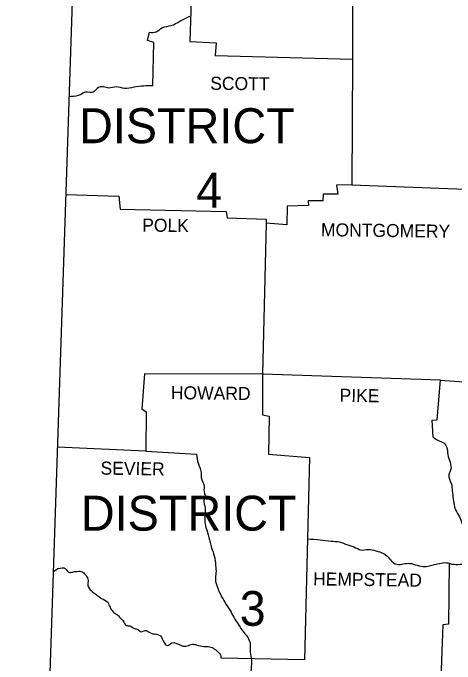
# Model space of a CAD drawing. Extents: x -0.54 to 1.64, y 0 to 0.92.
# Drawn here: x 1.0951 to 1.1608, y 0.624 to 0.7208 of the extents above; entities that cross this region are included whole.
import ezdxf

# ---------------------------------------------------------------- set-up
doc = ezdxf.new("R2010")
doc.units = 0
doc.layers.add('SHET_Annotations', color=7, linetype='Continuous')

msp = doc.modelspace()

# ---------------------------------------------------------------- linework, layer by layer
at = {"layer": 'SHET_Annotations'}
for p, q in [((1.103768, 0.708372), (1.103432, 0.708333)), ((1.101849, 0.638168), (1.101094, 0.637694))]:
    msp.add_line(p, q, dxfattribs=at)
for points in [[(1.095106, 0.817841), (1.104546, 0.741983), (1.100448, 0.618173)], [(1.140413, 0.741231), (1.140102, 0.734721), (1.134163, 0.73467), (1.133825, 0.728731), (1.127964, 0.728886), (1.127783, 0.722792), (1.12161, 0.722714), (1.121403, 0.716593), (1.125319, 0.716386), (1.125163, 0.714493), (1.145576, 0.713932)], [(1.170393, 0.734255), (1.170185, 0.727693), (1.159812, 0.727641), (1.158437, 0.726474), (1.157633, 0.724659), (1.156518, 0.724711), (1.156466, 0.723699), (1.155143, 0.723544), (1.155195, 0.72261), (1.148582, 0.722766), (1.148323, 0.72204), (1.1456, 0.721936), (1.145576, 0.713932)], [(1.115879, 0.70998), (1.116035, 0.716412), (1.115101, 0.716723), (1.115412, 0.717942)], [(1.145576, 0.713932), (1.145522, 0.69525), (1.143214, 0.695198), (1.143421, 0.693849), (1.141217, 0.693875), (1.141165, 0.692864), (1.139012, 0.692864), (1.139064, 0.692163), (1.1359, 0.69206), (1.135822, 0.689285), (1.132736, 0.68957), (1.132218, 0.667111)], [(1.145522, 0.69525), (1.16368, 0.694539)], [(1.102952, 0.693823), (1.110822, 0.693564), (1.111029, 0.691645), (1.126797, 0.691308), (1.126979, 0.690322), (1.132736, 0.690141), (1.132736, 0.68957)], [(1.15867, 0.666203), (1.132218, 0.667111), (1.11466, 0.667137), (1.114271, 0.661924), (1.114893, 0.661483), (1.114868, 0.655622), (1.101707, 0.656223)], [(1.132218, 0.667111), (1.132218, 0.661042), (1.133229, 0.660861), (1.133125, 0.655207), (1.139194, 0.654714), (1.138442, 0.624579), (1.126045, 0.624864)], [(1.157581, 0.657723), (1.157452, 0.660238), (1.158204, 0.66029), (1.15867, 0.666203), (1.165673, 0.665711), (1.165517, 0.662106), (1.174568, 0.661613), (1.174646, 0.659434), (1.182841, 0.658942), (1.184242, 0.656478), (1.183386, 0.655363), (1.183801, 0.653677), (1.204703, 0.652912)], [(1.114868, 0.655622), (1.122414, 0.655207)], [(1.159993, 0.638967), (1.159889, 0.629921), (1.159059, 0.629818), (1.158152, 0.605777)]]:
    msp.add_lwpolyline(points, dxfattribs=at)
for points in [[(1.115412, 0.717942), (1.116398, 0.71802), (1.117357, 0.718642), (1.118628, 0.718953), (1.119925, 0.719602), (1.121531, 0.720372)], [(1.115879, 0.70998), (1.114582, 0.709954), (1.113052, 0.709773), (1.111678, 0.709591), (1.110459, 0.709825), (1.109344, 0.709643), (1.108566, 0.709825), (1.107606, 0.709591), (1.107035, 0.709021), (1.105894, 0.709021), (1.10509, 0.708658), (1.103768, 0.708372)], [(1.157581, 0.657723), (1.158281, 0.657282), (1.159163, 0.656867), (1.15963, 0.656193), (1.159786, 0.655129), (1.160123, 0.653988), (1.160201, 0.652821), (1.159941, 0.652173), (1.160304, 0.650721), (1.160434, 0.649709), (1.16059, 0.648542), (1.160927, 0.646934), (1.161523, 0.645845), (1.162068, 0.644522), (1.162976, 0.64307), (1.163779, 0.64154), (1.164143, 0.640736), (1.164817, 0.63905), (1.165673, 0.637883), (1.167073, 0.636146), (1.168292, 0.634356), (1.168966, 0.633033), (1.17003, 0.631581), (1.171223, 0.630855), (1.172727, 0.630103), (1.173686, 0.62961), (1.17475, 0.628832), (1.176176, 0.62878), (1.177213, 0.62878), (1.178199, 0.628339), (1.17864, 0.627535), (1.17947, 0.626965), (1.180092, 0.626809)], [(1.122414, 0.655207), (1.122648, 0.653833), (1.123063, 0.652614), (1.123089, 0.651732), (1.12353, 0.650358), (1.123504, 0.649865), (1.123659, 0.648827), (1.123478, 0.648309), (1.123685, 0.647219), (1.123659, 0.646364), (1.123633, 0.645689), (1.123711, 0.644548), (1.124048, 0.643537), (1.124411, 0.642059), (1.124645, 0.641255), (1.125034, 0.640062), (1.125241, 0.638609), (1.125293, 0.637546), (1.125215, 0.636535), (1.125501, 0.635393), (1.125993, 0.634252), (1.126616, 0.633163), (1.127394, 0.631918), (1.127938, 0.630933), (1.128613, 0.629895), (1.129157, 0.62904), (1.130013, 0.627924), (1.130376, 0.627017), (1.130376, 0.625772), (1.130558, 0.624553), (1.130506, 0.623256), (1.130428, 0.622037), (1.130091, 0.620429), (1.130298, 0.619651), (1.13118, 0.61851), (1.131725, 0.618173), (1.132684, 0.617992), (1.133125, 0.617343), (1.133411, 0.61641), (1.13437, 0.616073), (1.135433, 0.615995), (1.135952, 0.615424), (1.136626, 0.614698), (1.137039, 0.614094)], [(1.138891, 0.642598), (1.140802, 0.642448), (1.14241, 0.642266), (1.143629, 0.642136), (1.144899, 0.641696), (1.146066, 0.641281), (1.146793, 0.640943), (1.148011, 0.641021), (1.149075, 0.640814), (1.150242, 0.640399), (1.151124, 0.639621), (1.151694, 0.639024), (1.152731, 0.638791), (1.153613, 0.638946), (1.154651, 0.638843), (1.155818, 0.638506), (1.156803, 0.638532), (1.157581, 0.638713), (1.158489, 0.638921), (1.159604, 0.63905), (1.16046, 0.638843), (1.161601, 0.638817), (1.16295, 0.638921), (1.164779, 0.63912)], [(1.101849, 0.638168), (1.10286, 0.638194), (1.103508, 0.637598), (1.103949, 0.63765), (1.104649, 0.637754), (1.105376, 0.637702), (1.105842, 0.637287), (1.106257, 0.636586), (1.106231, 0.635886), (1.106257, 0.635601), (1.106595, 0.63503), (1.107139, 0.634564), (1.107736, 0.634123), (1.108254, 0.633734), (1.109188, 0.633163), (1.109292, 0.632982), (1.109629, 0.63223), (1.110096, 0.631659), (1.11064, 0.63127), (1.111237, 0.630648), (1.111496, 0.630362), (1.111963, 0.629714), (1.112456, 0.629662), (1.113182, 0.629247), (1.113675, 0.629117), (1.114193, 0.62878), (1.114738, 0.628962), (1.115438, 0.628651), (1.116346, 0.628417), (1.116864, 0.628288), (1.117435, 0.627432), (1.118057, 0.626706), (1.118758, 0.62712), (1.120158, 0.626706), (1.121014, 0.62668), (1.121792, 0.626913), (1.122388, 0.626835), (1.123478, 0.626576), (1.124152, 0.626576), (1.124904, 0.626317), (1.125578, 0.625772), (1.126019, 0.625149), (1.126045, 0.624864)]]:
    msp.add_spline(points, degree=3, dxfattribs=at)

# ---------------------------------------------------------------- texts
for s, rotation, p in [('SCOTT', 359.31996, (1.124432, 0.709395)), ('POLK', 359.32331, (1.114308, 0.688302)), ('MONTGOMERY', 359.27067, (1.140901, 0.687616)), ('HOWARD', 359.30301, (1.118582, 0.663379)), ('PIKE', 359.17368, (1.143671, 0.662989)), ('SEVIER', 359.18154, (1.108111, 0.652149)), ('HEMPSTEAD', 359.25715, (1.139731, 0.635681))]:
    msp.add_text(s, height=0.0019451, rotation=rotation, dxfattribs=at).set_placement(p)
for s, height, p in [('DISTRICT', 0.0052027, (1.104928, 0.701445)), ('4', 0.005203, (1.122341, 0.691861)), ('DISTRICT', 0.0052027, (1.105197, 0.643811)), ('3', 0.005157, (1.128838, 0.629663))]:
    msp.add_text(s, height=height, dxfattribs=at).set_placement(p)

doc.saveas('drawing.dxf')
